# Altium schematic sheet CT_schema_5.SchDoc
size 266 x 267 mm
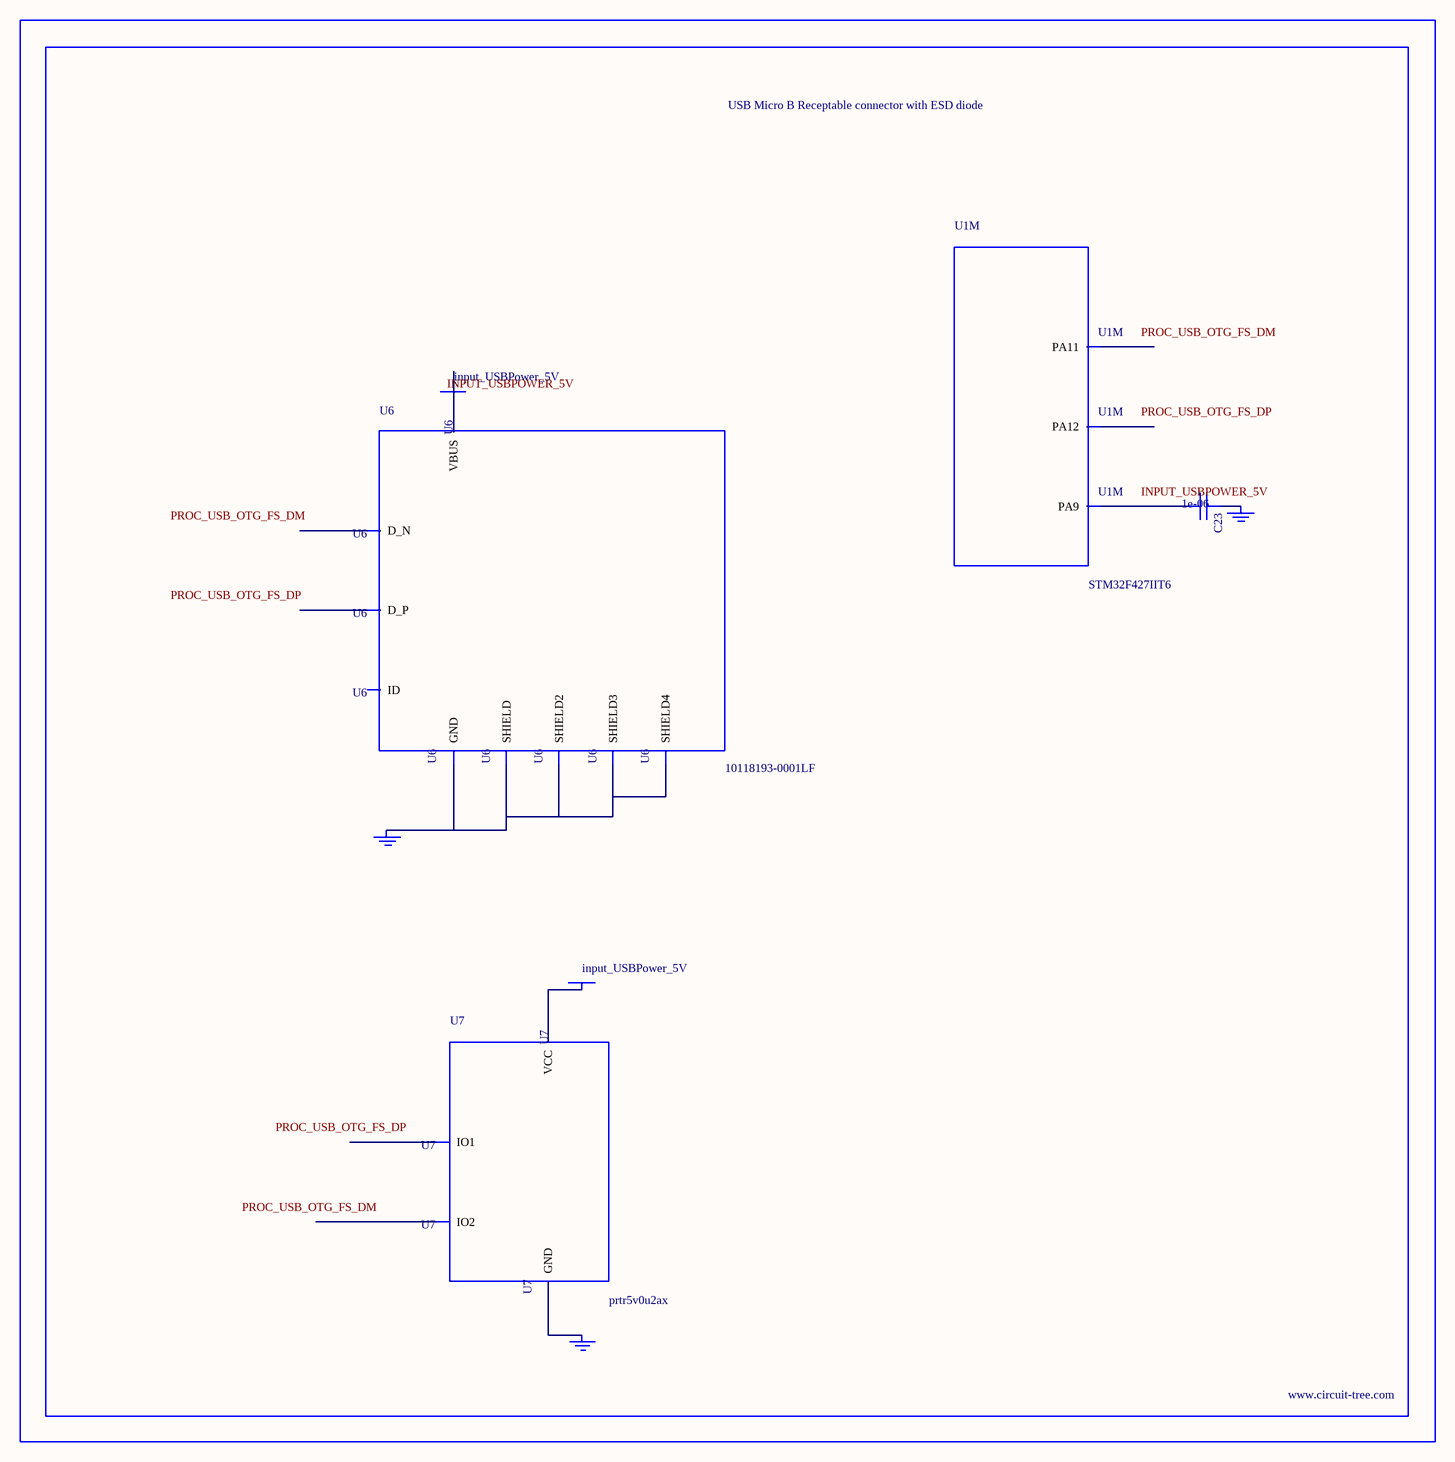
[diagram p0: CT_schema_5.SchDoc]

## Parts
BORDER4  (no value)
C23  1e-06  [C0603]
GND_INSTANCE_4_0  (no value)
GND_INSTANCE_4_1  (no value)
GND_INSTANCE_4_2  (no value)
POWER_INSTANCE_4_0  input_USBPower_5V
POWER_INSTANCE_4_1  input_USBPower_5V
U1  STM32F427IIT6  [LQFP176]  (part M of 14)
U6  10118193-0001LF  [FCI_10118193-0001LF]
U7  prtr5v0u2ax  [SOT143B]

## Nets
NetC23_1: C23.1 GND_INSTANCE_4_1.0(GND)
NetC23_2: C23.2 U1.120(PA9)
NetGND_INSTANCE_4_0_0: GND_INSTANCE_4_0.0(GND) U6.5(GND) U6.6(SHIELD) U6.7(SHIELD2) U6.8(SHIELD3) U6.9(SHIELD4)
NetGND_INSTANCE_4_2_0: GND_INSTANCE_4_2.0(GND) U7.1(GND)
NetPOWER_INSTANCE_4_0_0: POWER_INSTANCE_4_0.0(PWR) U6.1(VBUS)
NetPOWER_INSTANCE_4_1_0: POWER_INSTANCE_4_1.0(PWR) U7.4(VCC)

Not connected (* = marked no-connect by the designer): U1 122(PA11) 123(PA12); U6 2(D_N) 3(D_P) 4(ID); U7 2(IO1) 3(IO2)

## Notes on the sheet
- Labels drawn without touching a wire or pin: INPUT_USBPOWER_5V, PROC_USB_OTG_FS_DM, PROC_USB_OTG_FS_DP

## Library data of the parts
BORDER4 = BORDER_PAGE4
C23 = C0603C105K3RACTU
GND_INSTANCE_4_0-GND_INSTANCE_4_2 = GND
POWER_INSTANCE_4_0 POWER_INSTANCE_4_1 = PWR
